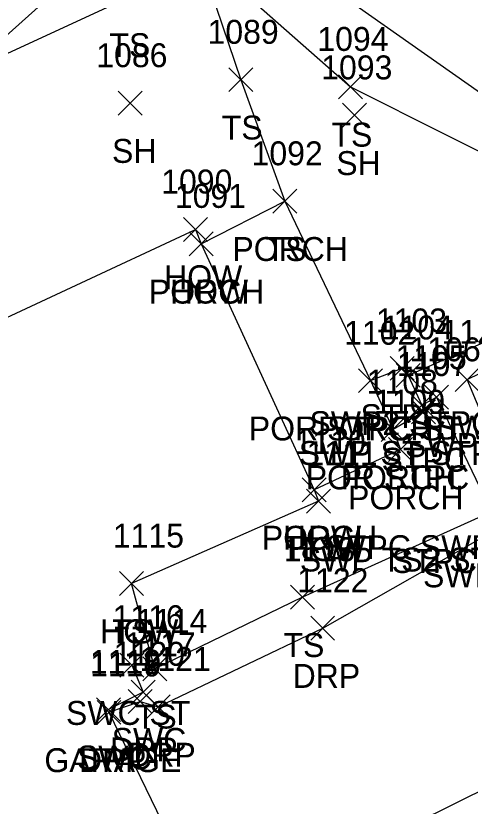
# Model space of a CAD drawing. Extents: x 1504228 to 1506103, y 437717 to 440106.
# Drawn here: x 1505043.8 to 1505081.8, y 438311.9 to 438378 of the extents above; entities that cross this region are included whole.
import ezdxf

# ---------------------------------------------------------------- set-up
doc = ezdxf.new("R2010")
doc.units = 0
for name, color, linetype in [('L_A', 7, 'Continuous'), ('L_I', 7, 'Continuous'), ('L_TIC', 7, 'Continuous'), ('LBC', 7, 'Continuous'), ('LBF', 7, 'Continuous'), ('LELB', 7, 'Continuous'), ('PET', 7, 'Continuous'), ('R_A', 7, 'Continuous'), ('R_I', 7, 'Continuous'), ('R_TIC', 7, 'Continuous'), ('RDP', 7, 'Continuous'), ('RSW', 7, 'Continuous')]:
    doc.layers.add(name, color=color, linetype=linetype)

msp = doc.modelspace()

# ---------------------------------------------------------------- linework, layer by layer
at = {"layer": 'L_TIC'}
for points in [[(1505061.619, 438371.642), (1505063.619, 438373.642)], [(1505063.619, 438371.642), (1505061.619, 438373.642)], [(1505070.79, 438371.048), (1505072.79, 438373.048)], [(1505072.79, 438371.048), (1505070.79, 438373.048)], [(1505052.363, 438369.689), (1505054.363, 438371.689)], [(1505054.363, 438369.689), (1505052.363, 438371.689)], [(1505071.114, 438368.67), (1505073.114, 438370.67)], [(1505073.114, 438368.67), (1505071.114, 438370.67)], [(1505065.294, 438361.487), (1505067.294, 438363.487)], [(1505067.294, 438361.487), (1505065.294, 438363.487)], [(1505065.294, 438361.487), (1505067.294, 438363.487)], [(1505067.294, 438361.487), (1505065.294, 438363.487)], [(1505057.823, 438359.128), (1505059.823, 438361.128)], [(1505059.823, 438359.128), (1505057.823, 438361.128)], [(1505058.311, 438357.927), (1505060.311, 438359.927)], [(1505060.311, 438357.927), (1505058.311, 438359.927)], [(1505058.311, 438357.927), (1505060.311, 438359.927)], [(1505060.311, 438357.927), (1505058.311, 438359.927)], [(1505075.113, 438347.515), (1505077.113, 438349.515)], [(1505077.113, 438347.515), (1505075.113, 438349.515)], [(1505075.603, 438346.927), (1505077.603, 438348.927)], [(1505077.603, 438346.927), (1505075.603, 438348.927)], [(1505072.458, 438346.483), (1505074.458, 438348.483)], [(1505074.458, 438346.483), (1505072.458, 438348.483)], [(1505072.458, 438346.483), (1505074.458, 438348.483)], [(1505074.458, 438346.483), (1505072.458, 438348.483)], [(1505076.756, 438344.437), (1505078.756, 438346.437)], [(1505078.756, 438344.437), (1505076.756, 438346.437)], [(1505076.883, 438343.869), (1505078.883, 438345.869)], [(1505078.883, 438343.869), (1505076.883, 438345.869)], [(1505074.346, 438342.395), (1505076.346, 438344.395)], [(1505076.346, 438342.395), (1505074.346, 438344.395)], [(1505074.346, 438342.395), (1505076.346, 438344.395)], [(1505076.346, 438342.395), (1505074.346, 438344.395)], [(1505074.967, 438340.717), (1505076.967, 438342.717)], [(1505076.967, 438340.717), (1505074.967, 438342.717)], [(1505067.758, 438337.349), (1505069.758, 438339.349)], [(1505069.758, 438337.349), (1505067.758, 438339.349)], [(1505067.758, 438337.349), (1505069.758, 438339.349)], [(1505069.758, 438337.349), (1505067.758, 438339.349)], [(1505068.109, 438336.414), (1505070.109, 438338.414)], [(1505070.109, 438336.414), (1505068.109, 438338.414)], [(1505052.478, 438329.527), (1505054.478, 438331.527)], [(1505054.478, 438329.527), (1505052.478, 438331.527)], [(1505052.478, 438329.527), (1505054.478, 438331.527)], [(1505054.478, 438329.527), (1505052.478, 438331.527)], [(1505066.779, 438328.379), (1505068.779, 438330.379)], [(1505068.779, 438328.379), (1505066.779, 438330.379)], [(1505054.432, 438322.4), (1505056.432, 438324.4)], [(1505056.432, 438322.4), (1505054.432, 438324.4)], [(1505050.598, 438318.755), (1505052.598, 438320.755)], [(1505052.598, 438318.755), (1505050.598, 438320.755)]]:
    msp.add_lwpolyline(points, dxfattribs=at)
at = {"layer": 'LBC'}
for points in [[(1505027.623, 438345.58), (1505058.823, 438360.128), (1505059.311, 438358.927), (1505068.758, 438338.349), (1505069.109, 438337.414), (1505053.478, 438330.527)], [(1505051.598, 438319.755), (1505060.879, 438300.637)]]:
    msp.add_lwpolyline(points, dxfattribs=at)
at = {"layer": 'LBF'}
for points in [[(1505059.311, 438358.927), (1505066.294, 438362.487), (1505073.458, 438347.483), (1505075.346, 438343.395), (1505075.967, 438341.717), (1505068.758, 438338.349)], [(1505073.458, 438347.483), (1505076.113, 438348.515), (1505076.603, 438347.927), (1505077.756, 438345.437), (1505077.883, 438344.869), (1505075.346, 438343.395)]]:
    msp.add_lwpolyline(points, dxfattribs=at)
at = {"layer": 'LELB'}
for points in [[(1505039.492, 438373.185), (1505053.227, 438379.528), (1505059.009, 438383.324), (1505062.619, 438372.642), (1505066.294, 438362.487)], [(1505059.009, 438383.324), (1505071.79, 438372.048), (1505087.996, 438363.895), (1505093.24, 438355.147)], [(1505083.583, 438336.527), (1505067.779, 438329.379), (1505055.432, 438323.4), (1505053.478, 438330.527)]]:
    msp.add_lwpolyline(points, dxfattribs=at)
at = {"layer": 'PET'}
msp.add_lwpolyline([(1505001.775, 438421.501), (1505032.758, 438402.461), (1505059.812, 438387.625), (1505089.41, 438366.798), (1505108.599, 438355.578), (1505130.106, 438339.585)], dxfattribs=at)
at = {"layer": 'R_TIC'}
for points in [[(1505075.603, 438346.927), (1505077.603, 438348.927)], [(1505077.603, 438346.927), (1505075.603, 438348.927)], [(1505080.538, 438346.565), (1505082.538, 438348.565)], [(1505082.538, 438346.565), (1505080.538, 438348.565)], [(1505077.986, 438345.099), (1505079.986, 438347.099)], [(1505079.986, 438345.099), (1505077.986, 438347.099)], [(1505076.756, 438344.437), (1505078.756, 438346.437)], [(1505078.756, 438344.437), (1505076.756, 438346.437)], [(1505068.466, 438325.799), (1505070.466, 438327.799)], [(1505070.466, 438325.799), (1505068.466, 438327.799)], [(1505052.508, 438322.704), (1505054.508, 438324.704)], [(1505054.508, 438322.704), (1505052.508, 438324.704)], [(1505053.459, 438320.448), (1505055.459, 438322.448)], [(1505055.459, 438320.448), (1505053.459, 438322.448)], [(1505053.209, 438319.651), (1505055.209, 438321.651)], [(1505055.209, 438319.651), (1505053.209, 438321.651)], [(1505054.718, 438319.206), (1505056.718, 438321.206)], [(1505056.718, 438319.206), (1505054.718, 438321.206)], [(1505050.551, 438318.979), (1505052.551, 438320.979)], [(1505052.551, 438318.979), (1505050.551, 438320.979)], [(1505050.598, 438318.755), (1505052.598, 438320.755)], [(1505052.598, 438318.755), (1505050.598, 438320.755)]]:
    msp.add_lwpolyline(points, dxfattribs=at)
at = {"layer": 'RDP'}
for points in [[(1505059.812, 438387.625), (1505051.559, 438384.007), (1505039.492, 438373.185), (1505022.739, 438357.365)], [(1505051.598, 438319.755), (1505054.209, 438320.651), (1505055.718, 438320.206), (1505069.466, 438326.799), (1505084.27, 438335.209), (1505086.379, 438336.405), (1505098.031, 438340.705), (1505102.72, 438347.262)], [(1505067.199, 438305.522), (1505087.097, 438315.384), (1505094.485, 438319.042), (1505105.46, 438324.312), (1505110.391, 438325.76), (1505115.64, 438325.797), (1505117.993, 438324.088)]]:
    msp.add_lwpolyline(points, dxfattribs=at)
at = {"layer": 'RSW'}
for points in [[(1505096.876, 438357.305), (1505093.24, 438355.147), (1505076.603, 438347.927)], [(1505085.734, 438337.561), (1505081.538, 438347.565), (1505093.336, 438353.326), (1505097.995, 438355.39)], [(1505077.756, 438345.437), (1505078.986, 438346.099), (1505083.583, 438336.527), (1505084.27, 438335.209)], [(1505053.508, 438323.704), (1505054.459, 438321.448), (1505051.551, 438319.979)]]:
    msp.add_lwpolyline(points, dxfattribs=at)

# ---------------------------------------------------------------- texts
at = {"layer": 'L_A'}
for s, p in [('TS', (1505051.637, 438374.528)), ('TS', (1505061.028, 438367.642)), ('TS', (1505070.199, 438367.048)), ('SH', (1505051.851, 438365.689)), ('SH', (1505070.602, 438364.67)), ('PORCH', (1505061.916, 438357.487)), ('TS', (1505064.703, 438357.487)), ('HOW', (1505056.209, 438355.128)), ('PORCH', (1505054.933, 438353.927)), ('HOW', (1505056.696, 438353.927)), ('SWP2 STPC', (1505068.359, 438342.927)), ('STPC', (1505072.625, 438343.515)), ('POR STPC ST', (1505063.293, 438342.483)), ('PORCH', (1505069.08, 438342.483)), ('SWP ST STPC', (1505067.465, 438340.437)), ('STPC', (1505074.394, 438339.869)), ('POR STPC', (1505068.046, 438338.395)), ('PORCH', (1505070.968, 438338.395)), ('PORCH', (1505071.589, 438336.717)), ('PORCH', (1505064.38, 438333.349)), ('HOW', (1505066.144, 438333.349)), ('HOW', (1505066.495, 438332.414)), ('STPC SWP ST TS ST', (1505069.71, 438332.561)), ('STPC ST  DRP', (1505075.237, 438331.405)), ('HOW', (1505050.864, 438325.527)), ('TS', (1505051.887, 438325.527)), ('TS', (1505066.189, 438324.379)), ('TS', (1505053.842, 438318.4)), ('GARAGE', (1505046.196, 438314.755))]:
    msp.add_text(s, height=2, dxfattribs=at).set_placement(p)
at = {"layer": 'L_I'}
for s, p in [('1089', (1505059.839, 438375.642)), ('1094', (1505069.018, 438375.048)), ('1086', (1505050.536, 438373.689)), ('1093', (1505069.342, 438372.67)), ('1092', (1505063.522, 438365.487)), ('1092', (1505063.522, 438365.487)), ('1090', (1505055.965, 438363.128)), ('1091', (1505057.106, 438361.927)), ('1091', (1505057.106, 438361.927)), ('1103', (1505073.908, 438351.515)), ('1104', (1505074.399, 438350.927)), ('1102', (1505071.253, 438350.483)), ('1102', (1505071.253, 438350.483)), ('1105', (1505075.551, 438348.437)), ('1107', (1505075.678, 438347.869)), ('1108', (1505073.141, 438346.395)), ('1108', (1505073.141, 438346.395)), ('1109', (1505073.755, 438344.717)), ('1110', (1505067.113, 438341.349)), ('1110', (1505067.113, 438341.349)), ('1111', (1505068.117, 438340.414)), ('1115', (1505051.919, 438333.527)), ('1115', (1505051.919, 438333.527)), ('1113', (1505066.22, 438332.379)), ('1114', (1505053.873, 438326.4)), ('1119', (1505050.031, 438322.755))]:
    msp.add_text(s, height=2, dxfattribs=at).set_placement(p)
at = {"layer": 'R_A'}
for s, p in [('SWP2 STPC', (1505068.359, 438342.927)), ('SWP', (1505078.901, 438342.565)), ('SWP', (1505076.348, 438341.099)), ('SWP ST STPC', (1505067.465, 438340.437)), ('STPC SWP ST TS ST', (1505069.71, 438332.561)), ('SWP TS2 ST SWC ST', (1505067.56, 438331.527)), ('SWP TS2 ST SWC ST', (1505067.56, 438331.527)), ('SWP DRP', (1505077.853, 438330.209)), ('DRP', (1505066.954, 438321.799)), ('SWC ST', (1505048.004, 438318.704)), ('SWC', (1505051.822, 438316.448)), ('DRP', (1505051.698, 438315.651)), ('DRP', (1505053.206, 438315.206)), ('SWC', (1505048.913, 438314.979)), ('DRP', (1505049.086, 438314.755))]:
    msp.add_text(s, height=2, dxfattribs=at).set_placement(p)
at = {"layer": 'R_I'}
for s, p in [('1104', (1505074.399, 438350.927)), ('1129', (1505079.405, 438350.565)), ('1106', (1505076.726, 438349.099)), ('1105', (1505075.551, 438348.437)), ('1122', (1505067.34, 438329.799)), ('1116', (1505051.894, 438326.704)), ('1117', (1505052.9, 438324.448)), ('1120', (1505051.997, 438323.651)), ('1121', (1505054.159, 438323.206)), ('1118', (1505049.992, 438322.979)), ('1119', (1505050.031, 438322.755))]:
    msp.add_text(s, height=2, dxfattribs=at).set_placement(p)

doc.saveas('drawing.dxf')
